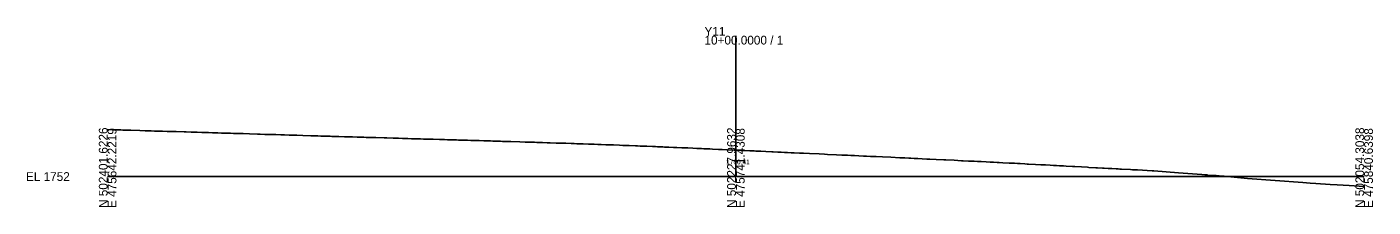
# Model space of a CAD drawing. Extents: x -76 to 353, y -10 to 8186.
# Drawn here: x -75.7 to 352.8, y -9.7 to 47.6 of the extents above; entities that cross this region are included whole.
import ezdxf

# ---------------------------------------------------------------- set-up
doc = ezdxf.new("R2010")
doc.units = 0
for name, color, linetype in [('Exist Cross Section Cell', 7, 'Continuous'), ('Exist XS Center Line Elevation Label', 7, 'Continuous'), ('Exist XS Ground Line', 7, 'Continuous'), ('Scratch_Level_5', 7, 'Continuous')]:
    doc.layers.add(name, color=color, linetype=linetype)

msp = doc.modelspace()

# ---------------------------------------------------------------- linework, layer by layer
at = {"layer": 'Exist Cross Section Cell'}
for p, q in [((150, 0), (150, 44.78)), ((-50, 0), (150, 0)), ((150, 0), (350, 0))]:
    msp.add_line(p, q, dxfattribs=at)
at = {"layer": 'Exist XS Ground Line'}
for points in [[(-50, 14.93), (-48.31, 14.87), (-45.8, 14.81), (-45.19, 14.79), (-42.6, 14.72), (-39.73, 14.63), (-38.04, 14.58), (-36.8, 14.54), (-36.19, 14.53), (-35.13, 14.49), (-34.36, 14.47), (-33.93, 14.46), (-32.54, 14.42), (-31.04, 14.37), (-30.69, 14.36), (-30.07, 14.34), (-28.17, 14.28), (-25.68, 14.2), (-25.04, 14.18), (-23.36, 14.13), (-22.39, 14.1), (-21.51, 14.08), (-20.01, 14.03), (-19.54, 14.02), (-17.89, 13.97), (-16.66, 13.93), (-16.03, 13.92), (-14.94, 13.88), (-13.77, 13.85), (-12.2, 13.8), (-10.91, 13.76), (-9.93, 13.73), (-8.71, 13.7), (-8, 13.68), (-6.85, 13.65), (-4.89, 13.58), (-2.28, 13.5), (-1.39, 13.47), (0.62, 13.41), (2.31, 13.37), (3.5, 13.33), (5.18, 13.27), (5.92, 13.25), (6.35, 13.24), (7.78, 13.2), (9.26, 13.15), (9.62, 13.14), (10.26, 13.12), (12.14, 13.07), (14.65, 12.99), (15.25, 12.97), (16.93, 12.93), (17.89, 12.9), (18.78, 12.87), (20.79, 12.81), (21.38, 12.79), (23.65, 12.72), (25.36, 12.67), (26.1, 12.66), (26.52, 12.64), (27.93, 12.6), (29.41, 12.55), (29.77, 12.54), (30.41, 12.52), (31.61, 12.49), (32.31, 12.47), (33.46, 12.44), (35.42, 12.38), (38.04, 12.3), (38.92, 12.28), (40.92, 12.22), (42.6, 12.17), (43.82, 12.13), (44.45, 12.11), (45.54, 12.08), (46.7, 12.05), (48.26, 12), (49.56, 11.96), (50.53, 11.93), (51.75, 11.9), (52.44, 11.88), (53.59, 11.85), (55.6, 11.78), (57.27, 11.74), (58.22, 11.71), (60.63, 11.64), (61.09, 11.63), (61.7, 11.61), (63.95, 11.55), (64.57, 11.53), (65.67, 11.5), (66.41, 11.48), (66.84, 11.47), (68.25, 11.43), (69.72, 11.38), (70.09, 11.37), (70.73, 11.35), (71.93, 11.32), (72.62, 11.3), (75.11, 11.22), (75.75, 11.2), (77.4, 11.16), (78.35, 11.13), (81.23, 11.03), (82.91, 10.99), (84.12, 10.95), (84.75, 10.93), (85.84, 10.89), (86.58, 10.87), (87, 10.86), (88.42, 10.81), (89.89, 10.77), (90.88, 10.73), (92.76, 10.67), (95.28, 10.59), (95.9, 10.57), (97.56, 10.51), (98.51, 10.48), (99.4, 10.45), (101.39, 10.38), (103.07, 10.32), (104.27, 10.28), (104.9, 10.26), (106, 10.22), (106.67, 10.19), (107.16, 10.17), (108.57, 10.12), (110.04, 10.08), (111.04, 10.04), (112.91, 9.96), (114.06, 9.91), (116.06, 9.85), (118.08, 9.75), (118.67, 9.74), (119.56, 9.7), (121.61, 9.63), (123.4, 9.55), (124.43, 9.52), (125.05, 9.5), (126.15, 9.45), (126.69, 9.42), (127.32, 9.39), (128.61, 9.33), (130.19, 9.28), (130.55, 9.27), (131.19, 9.24), (132.82, 9.17), (133.5, 9.14), (134.68, 9.09), (136.24, 9.04), (137.58, 8.97), (139.07, 8.9), (139.77, 8.87), (141.14, 8.82), (141.75, 8.79), (142.53, 8.75), (144.44, 8.66), (144.74, 8.65), (145.62, 8.61), (147.11, 8.55), (149.42, 8.44), (150, 8.41), (151.61, 8.34), (152.3, 8.31), (154.44, 8.21), (155.81, 8.15), (156.32, 8.12), (157.12, 8.09), (157.91, 8.05), (159.56, 7.97), (161.4, 7.9), (161.87, 7.88), (163.3, 7.81), (164.46, 7.75), (165.46, 7.7), (166.43, 7.66), (167.63, 7.6), (168.5, 7.56), (170.24, 7.47), (170.79, 7.44), (171.48, 7.41), (173.39, 7.33), (176.52, 7.18), (178.2, 7.11), (179.15, 7.06), (182.02, 6.92), (183.68, 6.85), (184.9, 6.79), (185.51, 6.76), (186.59, 6.71), (187.34, 6.67), (187.78, 6.65), (189.18, 6.6), (190.67, 6.53), (191.02, 6.51), (191.62, 6.48), (192.85, 6.43), (193.55, 6.4), (194.69, 6.35), (196.65, 6.25), (199.3, 6.12), (202.17, 5.99), (203.83, 5.91), (205.05, 5.86), (205.66, 5.83), (206.73, 5.79), (207.49, 5.75), (207.93, 5.73), (209.34, 5.66), (210.83, 5.58), (211.17, 5.57), (211.77, 5.54), (213.71, 5.44), (216.24, 5.32), (216.84, 5.3), (219.46, 5.17), (221.85, 5.05), (222.33, 5.03), (224, 4.94), (225.23, 4.88), (225.84, 4.85), (226.9, 4.8), (228.1, 4.74), (229.66, 4.66), (230.96, 4.6), (231.96, 4.55), (233.15, 4.49), (233.85, 4.45), (234.99, 4.4), (236.97, 4.29), (238.67, 4.21), (239.63, 4.15), (240.49, 4.11), (242.02, 4.03), (242.69, 3.99), (243.2, 3.97), (245.39, 3.85), (247.07, 3.76), (247.83, 3.72), (248.51, 3.68), (250, 3.6), (251.15, 3.54), (251.5, 3.52), (252.09, 3.49), (253.03, 3.44), (254.26, 3.37), (255.11, 3.32), (257.14, 3.21), (257.89, 3.17), (259.97, 3.06), (261.94, 2.95), (262.37, 2.93), (264.63, 2.81), (265.16, 2.78), (266.7, 2.7), (267.22, 2.67), (268.54, 2.6), (269.63, 2.54), (271.01, 2.46), (271.71, 2.43), (272.18, 2.4), (272.76, 2.37), (275.57, 2.22), (276.27, 2.18), (277.11, 2.13), (277.8, 2.09), (282.47, 1.83), (283.08, 1.79), (287, 1.49), (290.93, 1.19), (298.34, 0.63), (300.24, 0.48), (301.72, 0.37), (302.9, 0.29), (303.88, 0.21), (304.71, 0.16), (305.41, 0.1), (306.02, 0.06), (306.54, 0.02), (312.9, -0.6), (330.48, -1.93), (332.83, -2.09), (334.59, -2.21), (339.21, -2.56), (341.42, -2.61), (345.22, -2.88), (350, -3.15)], [(0, 13.43), (0.62, 13.41), (2.31, 13.37), (3.5, 13.33), (5.18, 13.27), (5.92, 13.25), (6.35, 13.24), (7.78, 13.2), (9.26, 13.15), (9.62, 13.14), (10.26, 13.12), (12.14, 13.07), (14.65, 12.99), (15.25, 12.97), (16.93, 12.93), (17.89, 12.9), (18.78, 12.87), (20.79, 12.81), (21.38, 12.79), (23.65, 12.72), (25.36, 12.67), (26.1, 12.66), (26.52, 12.64), (27.93, 12.6), (29.41, 12.55), (29.77, 12.54), (30.41, 12.52), (31.61, 12.49), (32.31, 12.47), (33.46, 12.44), (35.42, 12.38), (38.04, 12.3), (38.92, 12.28), (40.92, 12.22), (42.6, 12.17), (43.82, 12.13), (44.45, 12.11), (45.54, 12.08), (46.7, 12.05), (48.26, 12), (49.56, 11.96), (50.53, 11.93), (51.75, 11.9), (52.44, 11.88), (53.59, 11.85), (55.6, 11.78), (57.27, 11.74), (58.22, 11.71), (60.63, 11.64), (61.09, 11.63), (61.7, 11.61), (63.95, 11.55), (64.57, 11.53), (65.67, 11.5), (66.41, 11.48), (66.84, 11.47), (68.25, 11.43), (69.72, 11.38), (70.09, 11.37), (70.73, 11.35), (71.93, 11.32), (72.62, 11.3), (75.11, 11.22), (75.75, 11.2), (77.4, 11.16), (78.35, 11.13), (81.23, 11.03), (82.91, 10.99), (84.12, 10.95), (84.75, 10.93), (85.84, 10.89), (86.58, 10.87), (87, 10.86), (88.42, 10.81), (89.89, 10.77), (90.88, 10.73), (92.76, 10.67), (95.28, 10.59), (95.9, 10.57), (97.56, 10.51), (98.51, 10.48), (99.4, 10.45), (101.39, 10.38), (103.07, 10.32), (104.27, 10.28), (104.9, 10.26), (106, 10.22), (106.67, 10.19), (107.16, 10.17), (108.57, 10.12), (110.04, 10.08), (111.04, 10.04), (112.91, 9.96), (114.06, 9.91), (116.06, 9.85), (118.08, 9.75), (118.67, 9.74), (119.56, 9.7), (121.61, 9.63), (123.4, 9.55), (124.43, 9.52), (125.05, 9.5), (126.15, 9.45), (126.69, 9.42), (127.32, 9.39), (128.61, 9.33), (130.19, 9.28), (130.55, 9.27), (131.19, 9.24), (132.82, 9.17), (133.5, 9.14), (134.68, 9.09), (136.24, 9.04), (137.58, 8.97), (139.07, 8.9), (139.77, 8.87), (141.14, 8.82), (141.75, 8.79), (142.53, 8.75), (144.44, 8.66), (144.74, 8.65), (145.62, 8.61), (147.11, 8.55), (149.42, 8.44), (150, 8.41), (151.61, 8.34), (152.3, 8.31), (154.44, 8.21), (155.81, 8.15), (156.32, 8.12), (157.12, 8.09), (157.91, 8.05), (159.56, 7.97), (161.4, 7.9), (161.87, 7.88), (163.3, 7.81), (164.46, 7.75), (165.46, 7.7), (166.43, 7.66), (167.63, 7.6), (168.5, 7.56), (170.24, 7.47), (170.79, 7.44), (171.48, 7.41), (173.39, 7.33), (176.52, 7.18), (178.2, 7.11), (179.15, 7.06), (182.02, 6.92), (183.68, 6.85), (184.9, 6.79), (185.51, 6.76), (186.59, 6.71), (187.34, 6.67), (187.78, 6.65), (189.18, 6.6), (190.67, 6.53), (191.02, 6.51), (191.62, 6.48), (192.85, 6.43), (193.55, 6.4), (194.69, 6.35), (196.65, 6.25), (199.3, 6.12), (202.17, 5.99), (203.83, 5.91), (205.05, 5.86), (205.66, 5.83), (206.73, 5.79), (207.49, 5.75), (207.93, 5.73), (209.34, 5.66), (210.83, 5.58), (211.17, 5.57), (211.77, 5.54), (213.71, 5.44), (216.24, 5.32), (216.84, 5.3), (219.46, 5.17), (221.85, 5.05), (222.33, 5.03), (224, 4.94), (225.23, 4.88), (225.84, 4.85), (226.9, 4.8), (228.1, 4.74), (229.66, 4.66), (230.96, 4.6), (231.96, 4.55), (233.15, 4.49), (233.85, 4.45), (234.99, 4.4), (236.97, 4.29), (238.67, 4.21), (239.63, 4.15), (240.49, 4.11), (242.02, 4.03), (242.69, 3.99), (243.2, 3.97), (245.39, 3.85), (247.07, 3.76), (247.83, 3.72), (248.51, 3.68), (250, 3.6), (251.15, 3.54), (251.5, 3.52), (252.09, 3.49), (253.03, 3.44), (254.26, 3.37), (255.11, 3.32), (257.14, 3.21), (257.89, 3.17), (259.97, 3.06), (261.94, 2.95), (262.37, 2.93), (264.63, 2.81), (265.16, 2.78), (266.7, 2.7), (267.22, 2.67), (268.54, 2.6), (269.63, 2.54), (271.01, 2.46), (271.71, 2.43), (272.18, 2.4), (272.76, 2.37), (275.57, 2.22), (276.27, 2.18), (277.11, 2.13), (277.8, 2.09), (282.47, 1.83), (283.08, 1.79), (287, 1.49), (290.93, 1.19), (298.34, 0.63), (300, 0.5)]]:
    msp.add_lwpolyline(points, dxfattribs=at)
at = {"layer": 'Scratch_Level_5'}
msp.add_lwpolyline([(-50, 14.93), (-48.31, 14.87), (-45.8, 14.81), (-45.19, 14.79), (-42.6, 14.72), (-39.73, 14.63), (-38.04, 14.58), (-36.8, 14.54), (-36.19, 14.53), (-35.13, 14.49), (-34.36, 14.47), (-33.93, 14.46), (-32.54, 14.42), (-31.04, 14.37), (-30.69, 14.36), (-30.07, 14.34), (-28.17, 14.28), (-25.68, 14.2), (-25.04, 14.18), (-23.36, 14.13), (-22.39, 14.1), (-21.51, 14.08), (-20.01, 14.03), (-19.54, 14.02), (-17.89, 13.97), (-16.66, 13.93), (-16.03, 13.92), (-14.94, 13.88), (-13.77, 13.85), (-12.2, 13.8), (-10.91, 13.76), (-9.93, 13.73), (-8.71, 13.7), (-8, 13.68), (-6.85, 13.65), (-4.89, 13.58), (-2.28, 13.5), (-1.39, 13.47), (0.62, 13.41), (2.31, 13.37), (3.5, 13.33), (5.18, 13.27), (5.92, 13.25), (6.35, 13.24), (7.78, 13.2), (9.26, 13.15), (9.62, 13.14), (10.26, 13.12), (12.14, 13.07), (14.65, 12.99), (15.25, 12.97), (16.93, 12.93), (17.89, 12.9), (18.78, 12.87), (20.79, 12.81), (21.38, 12.79), (23.65, 12.72), (25.36, 12.67), (26.1, 12.66), (26.52, 12.64), (27.93, 12.6), (29.41, 12.55), (29.77, 12.54), (30.41, 12.52), (31.61, 12.49), (32.31, 12.47), (33.46, 12.44), (35.42, 12.38), (38.04, 12.3), (38.92, 12.28), (40.92, 12.22), (42.6, 12.17), (43.82, 12.13), (44.45, 12.11), (45.54, 12.08), (46.7, 12.05), (48.26, 12), (49.56, 11.96), (50.53, 11.93), (51.75, 11.9), (52.44, 11.88), (53.59, 11.85), (55.6, 11.78), (57.27, 11.74), (58.22, 11.71), (60.63, 11.64), (61.09, 11.63), (61.7, 11.61), (63.95, 11.55), (64.57, 11.53), (65.67, 11.5), (66.41, 11.48), (66.84, 11.47), (68.25, 11.43), (69.72, 11.38), (70.09, 11.37), (70.73, 11.35), (71.93, 11.32), (72.62, 11.3), (75.11, 11.22), (75.75, 11.2), (77.4, 11.16), (78.35, 11.13), (81.23, 11.03), (82.91, 10.99), (84.12, 10.95), (84.75, 10.93), (85.84, 10.89), (86.58, 10.87), (87, 10.86), (88.42, 10.81), (89.89, 10.77), (90.88, 10.73), (92.76, 10.67), (95.28, 10.59), (95.9, 10.57), (97.56, 10.51), (98.51, 10.48), (99.4, 10.45), (101.39, 10.38), (103.07, 10.32), (104.27, 10.28), (104.9, 10.26), (106, 10.22), (106.67, 10.19), (107.16, 10.17), (108.57, 10.12), (110.04, 10.08), (111.04, 10.04), (112.91, 9.96), (114.06, 9.91), (116.06, 9.85), (118.08, 9.75), (118.67, 9.74), (119.56, 9.7), (121.61, 9.63), (123.4, 9.55), (124.43, 9.52), (125.05, 9.5), (126.15, 9.45), (126.69, 9.42), (127.32, 9.39), (128.61, 9.33), (130.19, 9.28), (130.55, 9.27), (131.19, 9.24), (132.82, 9.17), (133.5, 9.14), (134.68, 9.09), (136.24, 9.04), (137.58, 8.97), (139.07, 8.9), (139.77, 8.87), (141.14, 8.82), (141.75, 8.79), (142.53, 8.75), (144.44, 8.66), (144.74, 8.65), (145.62, 8.61), (147.11, 8.55), (149.42, 8.44), (150, 8.41), (151.61, 8.34), (152.3, 8.31), (154.44, 8.21), (155.81, 8.15), (156.32, 8.12), (157.12, 8.09), (157.91, 8.05), (159.56, 7.97), (161.4, 7.9), (161.87, 7.88), (163.3, 7.81), (164.46, 7.75), (165.46, 7.7), (166.43, 7.66), (167.63, 7.6), (168.5, 7.56), (170.24, 7.47), (170.79, 7.44), (171.48, 7.41), (173.39, 7.33), (176.52, 7.18), (178.2, 7.11), (179.15, 7.06), (182.02, 6.92), (183.68, 6.85), (184.9, 6.79), (185.51, 6.76), (186.59, 6.71), (187.34, 6.67), (187.78, 6.65), (189.18, 6.6), (190.67, 6.53), (191.02, 6.51), (191.62, 6.48), (192.85, 6.43), (193.55, 6.4), (194.69, 6.35), (196.65, 6.25), (199.3, 6.12), (202.17, 5.99), (203.83, 5.91), (205.05, 5.86), (205.66, 5.83), (206.73, 5.79), (207.49, 5.75), (207.93, 5.73), (209.34, 5.66), (210.83, 5.58), (211.17, 5.57), (211.77, 5.54), (213.71, 5.44), (216.24, 5.32), (216.84, 5.3), (219.46, 5.17), (221.85, 5.05), (222.33, 5.03), (224, 4.94), (225.23, 4.88), (225.84, 4.85), (226.9, 4.8), (228.1, 4.74), (229.66, 4.66), (230.96, 4.6), (231.96, 4.55), (233.15, 4.49), (233.85, 4.45), (234.99, 4.4), (236.97, 4.29), (238.67, 4.21), (239.63, 4.15), (240.49, 4.11), (242.02, 4.03), (242.69, 3.99), (243.2, 3.97), (245.39, 3.85), (247.07, 3.76), (247.83, 3.72), (248.51, 3.68), (250, 3.6), (251.15, 3.54), (251.5, 3.52), (252.09, 3.49), (253.03, 3.44), (254.26, 3.37), (255.11, 3.32), (257.14, 3.21), (257.89, 3.17), (259.97, 3.06), (261.94, 2.95), (262.37, 2.93), (264.63, 2.81), (265.16, 2.78), (266.7, 2.7), (267.22, 2.67), (268.54, 2.6), (269.63, 2.54), (271.01, 2.46), (271.71, 2.43), (272.18, 2.4), (272.76, 2.37), (275.57, 2.22), (276.27, 2.18), (277.11, 2.13), (277.8, 2.09), (282.47, 1.83), (283.08, 1.79), (287, 1.49), (290.93, 1.19), (298.34, 0.63), (300.24, 0.48), (301.72, 0.37), (302.9, 0.29), (303.88, 0.21), (304.71, 0.16), (305.41, 0.1), (306.02, 0.06), (306.54, 0.02), (312.9, -0.6), (330.48, -1.93), (332.83, -2.09), (334.59, -2.21), (339.21, -2.56), (341.42, -2.61), (345.22, -2.88), (350, -3.15)], dxfattribs=at)

# ---------------------------------------------------------------- texts
at = {"layer": 'Exist Cross Section Cell'}
for s, p in [('Y11', (140, 44.78)), ('10+00.0000 / 1', (140, 41.98)), ('EL 1752', (-76, -1.4))]:
    msp.add_text(s, height=2.8, dxfattribs=at).set_placement(p)
for s, p in [('N 502401.6226', (-50, -10)), ('E 475642.2219', (-47.2, -10)), ('N 502227.9632', (150, -10)), ('E 475741.4308', (152.8, -10)), ('N 502054.3038', (350, -10)), ('E 475840.6398', (352.8, -10))]:
    msp.add_text(s, height=2.8, rotation=90, dxfattribs=at).set_placement(p)
at = {"layer": 'Exist XS Center Line Elevation Label'}
msp.add_text('1760.41', height=1.5, dxfattribs=at).set_placement((146.91, 3.91))

doc.saveas('drawing.dxf')
